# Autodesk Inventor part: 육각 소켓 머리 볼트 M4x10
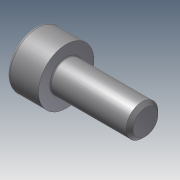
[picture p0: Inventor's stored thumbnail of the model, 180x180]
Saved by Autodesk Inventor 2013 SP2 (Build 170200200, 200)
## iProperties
Created: 2025-04
Part Number: 육각 소켓 머리 볼트 M4x10
Material: Generic
Document SubType Name: Modeling
Designer: i
Density: 1 g/cm^3
Author: i
변환 표준: STEP AP214IS
전처리기: Build: 200, Release: 2013 SP2 Update 6 - Date: Thu 07/17/2014
전송 단위: 밀리미터
불확실성: 0.01
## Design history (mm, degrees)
node "육각 소켓 머리 볼트 M4x101"
body "Solid1"
node "기준1"
